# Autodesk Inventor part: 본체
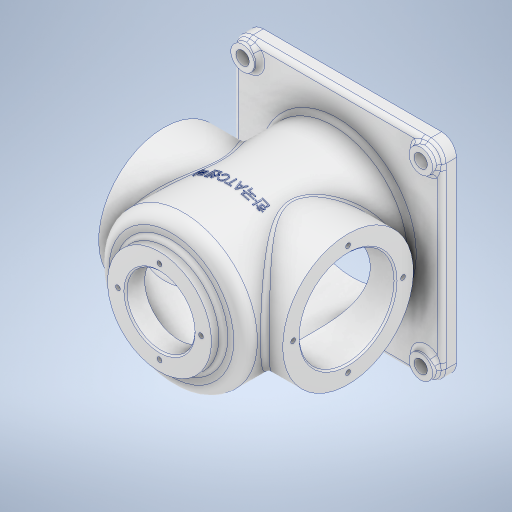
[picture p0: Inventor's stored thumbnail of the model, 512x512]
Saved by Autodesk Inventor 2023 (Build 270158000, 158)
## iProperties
Created: 2025-05
Part Number: 본체
Material: 알루미늄 6061
Document SubType Name: Modeling
Designer: Admin
Density: 2.7 g/cm^3
Appearance: 알루미늄 - 평지
Mass: 1130.88 g
Surface Area: 1201.39 cm^2
Volume: 418.845 cm^3
Author: Admin
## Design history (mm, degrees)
sketch "스케치1"
  geometry: L1 (-98, 0)-(98, 0) reference; L2 (0, -98)-(0, 98) reference; L3 (-70, -70)-(70, -70); L4 (70, -70)-(70, 70); L5 (70, 70)-(-70, 70); L6 (-70, 70)-(-70, -70); L7 (-70, -70)-(70, 70); L8 (70, -70)-(-70, 70); 1 further point
  constraints: 12 end point, 2 midpoint, 2 parallel, 1 horizontal, 1 perpendicular
  dimensions: "d0" = 140 distance of L4.end L5.end; "d1" = 140 distance of L3.end L4.end
extrude "돌출1" new body sketch "스케치1" distance "d2" = 10; taper "d3" = 0 deg
sketch "스케치2"
  geometry: L1 (-98, 0)-(98, 0) reference; L2 (0, -98)-(0, 98) reference; C1 r 50 at (0, 0); 1 further point
  constraints: 1 centre point, 1 coincident
  dimensions: "d4" = 100 diameter of C1
extrude "돌출2" join sketch "스케치2" distance "d5" = 112; taper "d6" = 0 deg
sketch "스케치3"
  geometry: L1 (-98, 0)-(98, 0) reference; L2 (0, -98)-(0, 98) reference; C1 r 35 at (0, 0); 1 further point
  constraints: 1 centre point, 1 coincident
  dimensions: "d7" = 70 diameter of C1
extrude "돌출3" join sketch "스케치3" distance "d8" = 8; taper "d9" = 0 deg
node "작업 평면1"
sketch "스케치4"
  geometry: L1 (-98, 0)-(98, 0) reference; L2 (0, -26)-(0, 156) reference; L3 (-70, 0)-(70, 0) reference; C1 r 44 at (0, 65); 2 further points
  constraints: 2 midpoint, 1 centre point
  dimensions: "d11" = 88 diameter of C1; "d12" = 65 distance of point (0, 0) C1.centre
extrude "돌출4" join sketch "스케치4" stored distance "d13" = 8; taper "d14" = 0 deg
sketch "스케치5" dims "d15" = 56
  geometry: L1 (-98, 0)-(98, 0) reference; L2 (0, -98)-(0, 98) reference; 3 further points
  constraints: 1 coincident, 1 horizontal alignment, 1 point on line, 2 other
hole "구멍1" sketch "스케치5" at (-28, 0) diameter "d16" = 3.242; stored, may be unused: countersink angle "d20" = 90 deg, drill point angle "d22" = 118 deg; dims "d17" = 8, "d18" = 4, "d19" = 2, "d21" = 10
sketch "스케치6" dims "d26" = 74
  geometry: L1 (65, -98)-(65, 98) reference; L2 (91, 0)-(-91, 0) reference; L3 (65, -70)-(65, 70) reference; 4 further points
  constraints: 2 midpoint, 1 horizontal alignment, 1 point on line, 2 other
  dimensions: "d27" = 65 distance of point (65, 0) point (0, 0)
hole "구멍2" sketch "스케치6" at (-37, 0) diameter "d28" = 3.242; stored, may be unused: countersink angle "d32" = 90 deg, drill point angle "d34" = 118 deg; dims "d29" = 8, "d30" = 4, "d31" = 2, "d33" = 10
sketch "스케치7"
  geometry: L1 (-98, 0)-(98, 0) reference; L2 (0, -98)-(0, 98) reference; C1 r 35 at (0, 0) reference; C2 r 23 at (0, 0); 1 further point
  constraints: 1 centre point, 1 coincident
  dimensions: "d38" = 46 diameter of C2
extrude "돌출5" cut sketch "스케치7" distance "d39" = 13; taper "d40" = 0 deg
sketch "스케치8"
  geometry: L1 (-70, 0)-(-70, 10) reference; L2 (-70, 10)-(-50, 10) reference; L3 (-50, 10)-(-50, 21) reference; L4 (-50, 21)-(-62, 21) reference; L5 (-62, 21)-(-62, 26.379) reference; L6 (-62, 26.379)-(-52, 26.379) reference; L7 (-52, 26.379)-(-51.026, 28) reference; L8 (-51.026, 28)-(-52, 29.621) reference; L9 (-52, 29.621)-(-62, 29.621) reference; L10 (-62, 29.621)-(-62, 100.379) reference; L11 (-62, 100.379)-(-52, 100.379) reference; L12 (-52, 100.379)-(-51.026, 102) reference; L13 (-51.026, 102)-(-52, 103.621) reference; L14 (-52, 103.621)-(-62, 103.621) reference; L15 (-62, 103.621)-(-62, 109) reference; L16 (-62, 109)-(-50, 109) reference; L17 (-50, 109)-(-50, 122) reference; L18 (-50, 122)-(-35, 122) reference; L19 (-35, 122)-(-35, 130) reference; L20 (-35, 130)-(-29.621, 130) reference; L21 (-29.621, 130)-(-29.621, 120) reference; L22 (-29.621, 120)-(-28, 119.026) reference; L23 (-28, 119.026)-(-26.379, 120) reference; L24 (-26.379, 120)-(-26.379, 130) reference; L25 (-26.379, 130)-(-23, 130) reference; L26 (-23, 130)-(-23, 117) reference; L27 (-23, 117)-(23, 117) reference; L28 (23, 117)-(23, 130) reference; L29 (23, 130)-(26.379, 130) reference; L30 (26.379, 130)-(26.379, 120) reference; L31 (26.379, 120)-(28, 119.026) reference; L32 (28, 119.026)-(29.621, 120) reference; L33 (29.621, 120)-(29.621, 130) reference; L34 (29.621, 130)-(35, 130) reference; L35 (35, 130)-(35, 122) reference; L36 (35, 122)-(50, 122) reference; L37 (50, 122)-(50, 109) reference; L38 (50, 109)-(62, 109) reference; L39 (62, 109)-(62, 103.621) reference; L40 (62, 103.621)-(52, 103.621) reference; L41 (52, 103.621)-(51.026, 102) reference; L42 (51.026, 102)-(52, 100.379) reference; L43 (52, 100.379)-(62, 100.379) reference; L44 (62, 100.379)-(62, 29.621) reference; L45 (62, 29.621)-(52, 29.621) reference; L46 (52, 29.621)-(51.026, 28) reference; L47 (51.026, 28)-(52, 26.379) reference; L48 (52, 26.379)-(62, 26.379) reference; L49 (62, 26.379)-(62, 21) reference; L50 (62, 21)-(50, 21) reference; L51 (50, 21)-(50, 10) reference; L52 (50, 10)-(70, 10) reference; L53 (70, 10)-(70, 0) reference; L54 (70, 0)-(-70, 0) reference; L55 (98, 0)-(-98, 0) reference; L56 (0, -26)-(0, 156) reference; L57 (0, 0)-(-45, 0); L58 (-45, 0)-(-45, 117); L59 (-45, 117)-(0, 117); L60 (0, 117)-(0, 0); 3 further points
  constraints: 8 end point, 2 parallel, 1 horizontal, 1 perpendicular
  dimensions: "d41" = 45 distance of L58.end L59.end; "d42" = 117 distance of L57.end L58.end
revolve "회전1" sketch "스케치8" stored, may be unused: angle "d43" = 90 deg
sketch "스케치9"
  geometry: L1 (65, -98)-(65, 98) reference; L2 (91, 0)-(-91, 0) reference; L3 (65, -70)-(65, 70) reference; C1 r 32 at (0, 0); 2 further points
  constraints: 2 midpoint, 1 centre point
  dimensions: "d44" = 64 diameter of C1; "d45" = 65 distance of point (65, 0) C1.centre
extrude "돌출6" cut sketch "스케치9" extent not by distance; stored distance "d46" = 0; taper "d47" = 0 deg
node "작업 평면2"
sketch "스케치10"
  geometry: L1 (-98, 0)-(98, 0) reference; L2 (0, -98)-(0, 98) reference; L3 (-60, 60)-(60, 60); L4 (60, 60)-(60, -60); L5 (60, -60)-(-60, -60); L6 (-60, -60)-(-60, 60); L7 (-60, 60)-(60, -60); L8 (60, 60)-(-60, -60); C1 r 8 at (-60, -60); C2 r 8 at (60, -60); C3 r 8 at (60, 60); C4 r 8 at (-60, 60); 5 further points
  constraints: 12 end point, 6 coincident, 4 centre point, 2 midpoint, 2 parallel, 2 symmetric about line, 1 horizontal, 1 perpendicular, 2 other
  dimensions: "d50" = 120 distance of L3.end L4.end; "d51" = 120 distance of L4.end L5.end; "d52" = 16 diameter of C1; "d53" = 16 diameter of C2
extrude "돌출7" join sketch "스케치10" extent not by distance; stored distance "d54" = 0; taper "d55" = 0 deg
fillet "모깎기2" dims "d56" = 10
sketch "스케치11"
  geometry: L1 (98, 0)-(-98, 0) reference; L2 (0, -98)-(0, 98) reference; L3 (-60, 60)-(60, 60); L4 (60, 60)-(60, -60); L5 (60, -60)-(-60, -60); L6 (-60, -60)-(-60, 60); L7 (-60, 60)-(60, -60); L8 (60, 60)-(-60, -60); C1 r 8 at (60, 60) reference; C2 r 4.5 at (60, 60); C3 r 4.5 at (-60, 60); C4 r 4.5 at (60, -60); C5 r 4.5 at (-60, -60); 1 further point
  constraints: 12 end point, 4 centre point, 2 coincident, 2 midpoint, 2 parallel, 2 symmetric about line, 1 horizontal, 1 perpendicular, 2 other
  dimensions: "d57" = 120 distance of L3.end L4.end; "d58" = 120 distance of L4.end L5.end; "d59" = 9 diameter of C2; "d60" = 9 diameter of C3
extrude "돌출8" cut sketch "스케치11" distance "d61" = 14; taper "d62" = 0 deg
fillet "모깎기3" dims "d63" = 3
fillet "모깎기4" dims "d64" = 8
fillet "모깎기5" dims "d65" = 3
chamfer "모따기1" distance "d66" = 1; stored, may be unused: second distance "d67" = 2, angle "d68" = 45 deg
chamfer "모따기2" distance "d69" = 1; stored, may be unused: second distance "d70" = 2, angle "d71" = 45 deg
fillet "모깎기6" dims "d72" = 3
node "작업 평면3"
sketch "스케치12"
  geometry: L1 (98, 0)-(-98, 0) reference; L2 (0, -26)-(0, 156) reference; 2 further points
  constraints: 1 other
  dimensions: "d80" = 80 vertical distance of point (0, 0) point (1.549, 80)
feature "엠보싱1" sketch "스케치12" dims "d81" = 0.5, "d82" = 0
fillet "모깎기7" dims "d83" = 3
fillet "모깎기8" dims "d84" = 3
fillet "모깎기9" dims "d85" = 3
fillet "모깎기10" dims "d86" = 3
feature "ӊ耀ӌ耀ӎ耀Ӑ耀Ӓ耀Ӕ耀Ӗ耀Ә耀" dims "d0" = 140, "d1" = 140, "d2" = 10, "d3" = 0, "d4" = 100, "d5" = 112, "d6" = 0, "d7" = 70, "d8" = 8, "d9" = 0, "d10" = 62, "d11" = 88, "d12" = 65, "d13" = 8, "d14" = 0, "d15" = 56, "d16" = 3.242, "d17" = 8, "d18" = 4, "d19" = 2, "d20" = 90 deg, "d21" = 10, "d22" = 118 deg, "d23" = 40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
node "솔리드1"
mirror "미러1"
pattern_circular "원형 패턴1" dims angle "d24" = 360 deg
pattern_circular "원형 패턴2" dims angle "d36" = 360 deg
mirror "미러2"
node "절단 모서리 투영1"
feature "A9D066F2-1C7D-4E18-AEED-F7BC21143FA4" dims "d16" = 3.242, "d17" = 8, "d18" = 4, "d19" = 2, "d20" = 90 deg, "d21" = 10, "d22" = 118 deg
